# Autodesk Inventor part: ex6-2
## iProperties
Author: Administrator
Created: 2001-03
Part Number: ex6-2
Document SubType Name: Modeling
Designer: Administrator
Control State: 0
Master: False
Checked Out: False
PropertySet Name: Design Tracking Control
Shininess: 20.0
PropertySet Name: _Private Model Information
Density: 0.0
Volumn: 0.0
Area: 0.0
PropertySet Name: Model Information
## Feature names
1. Extrusion1
2. Hole1
3. Hole2
4. Fillet1
